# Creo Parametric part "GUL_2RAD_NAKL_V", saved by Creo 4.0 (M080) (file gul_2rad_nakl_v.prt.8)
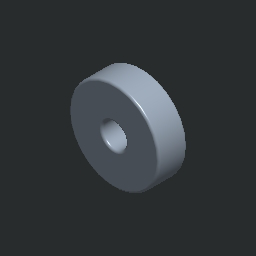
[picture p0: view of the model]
Units: Custom; MM, KILOGRAM, SECS
Materials in the file: OCEL_N

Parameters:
  MFG_WP_MATERIAL = "RO6"
  NAZOV = "GUL_2RAD_NAKL_V"
  PTC_MATERIAL_NAME = "OCEL_N"

Other parameters: HMOTNOST, HUSTOTA

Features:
  1. round

Named dimensions: velke_D

Layers: 1, 2, 3, 4, 5, 6, 7, 8, 9, 10, 11, 12, 13, 14, 15, 16, 17, 18, 19, 20, 21, 22, 23, 24, 25, 26, 27, 28, 29, 30, 31, 32

Family table entries: GENERIC, LOZISKO_135, GUL_2RAD_NAKL_V, value(d_val), 2/3, value(i_val), LOZISKO_126, GUL_2RAD_NAKL_V, 2/3, LOZISKO_127, GUL_2RAD_NAKL_V, 2/6, LOZISKO_108, GUL_2RAD_NAKL_V, !/ , 2/6, LOZISKO_129, GUL_2RAD_NAKL_V, !/", 2/:, 2/ , LOZISKO_1200, GUL_2RAD_NAKL_V, !/$, 2/>, 2/", LOZISKO_2200, GUL_2RAD_NAKL_V, !/$, 2/>, 2/,, LOZISKO_1300, GUL_2RAD_NAKL_V, !/$, 2/&, LOZISKO_1201, GUL_2RAD_NAKL_V, !/(, 2/@, 2/$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

Surfaces: 8 torus, 2 plane, 2 cylinder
